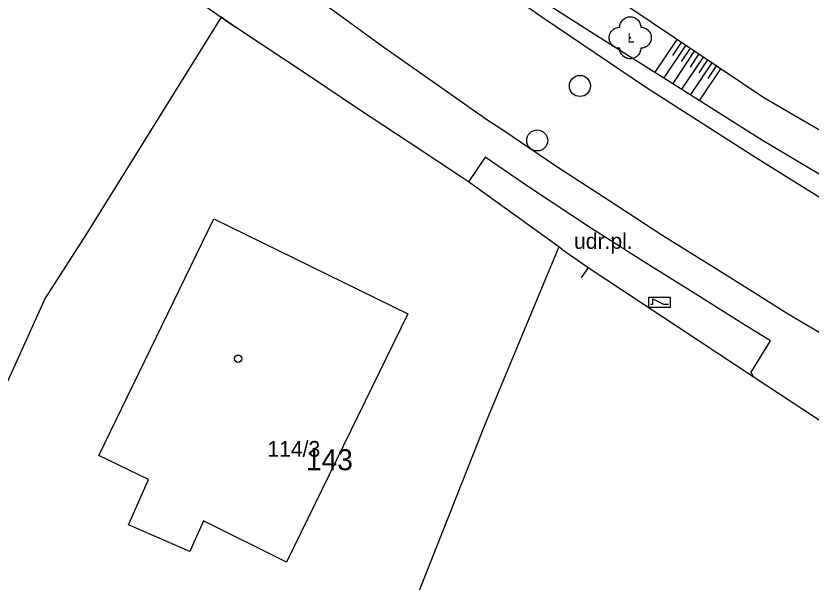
# Model space of a CAD drawing. Extents: x -836568 to -836015, y -1070547 to -1070212.
# Drawn here: x -836460.84 to -836423.06, y -1070392.19 to -1070365.29 of the extents above; entities that cross this region are included whole.
import ezdxf

# ---------------------------------------------------------------- set-up
doc = ezdxf.new("R2010")
doc.units = 0
for name, color, linetype in [('BodPole_mer', 7, 'Continuous'), ('Budovy_hranice', 7, 'Continuous'), ('Budovy_kody', 7, 'Continuous'), ('Doprava_hranice', 7, 'Continuous'), ('PovrZnIS_body', 7, 'Continuous'), ('PovrZnIS_hranice', 7, 'Continuous'), ('RuianAdr_popis', 7, 'Continuous'), ('RuianPar_popis', 7, 'Continuous'), ('Stavby_linie', 7, 'Continuous'), ('Vyskopis_linie', 7, 'Continuous'), ('Zelen_body', 7, 'Continuous'), ('Zelen_kody', 7, 'Continuous')]:
    doc.layers.add(name, color=color, linetype=linetype)

msp = doc.modelspace()

# ---------------------------------------------------------------- linework, layer by layer
at = {"layer": 'BodPole_mer'}
for p, q in [((-836451.09, -1070365.35), (-836451.09, -1070365.35)), ((-836435.85, -1070365.34), (-836435.85, -1070365.34)), ((-836450.4, -1070365.82), (-836450.4, -1070365.82)), ((-836450.4, -1070365.82), (-836450.4, -1070365.82)), ((-836433.66, -1070365.96), (-836433.66, -1070365.96)), ((-836431.65, -1070366.33), (-836431.65, -1070366.33)), ((-836443.36, -1070366.79), (-836443.36, -1070366.79)), ((-836433.37, -1070367.02), (-836433.37, -1070367.02)), ((-836446.93, -1070368.12), (-836446.93, -1070368.12)), ((-836446.93, -1070368.12), (-836446.93, -1070368.12)), ((-836440.92, -1070368.5), (-836440.92, -1070368.5)), ((-836434.04, -1070368.62), (-836434.04, -1070368.62)), ((-836430.87, -1070368.7), (-836430.87, -1070368.7)), ((-836425.3, -1070369.18), (-836425.3, -1070369.18)), ((-836444.56, -1070369.72), (-836444.56, -1070369.72)), ((-836444.56, -1070369.72), (-836444.56, -1070369.72)), ((-836438.47, -1070370.23), (-836438.47, -1070370.23)), ((-836428.32, -1070370.32), (-836428.32, -1070370.32)), ((-836437.61, -1070370.78), (-836437.61, -1070370.78)), ((-836436.07, -1070371.21), (-836436.07, -1070371.21)), ((-836425.36, -1070371.19), (-836425.36, -1070371.19)), ((-836442.16, -1070371.3), (-836442.16, -1070371.3)), ((-836442.16, -1070371.3), (-836442.16, -1070371.3)), ((-836438.55, -1070372.01), (-836438.55, -1070372.01)), ((-836425.77, -1070371.95), (-836425.77, -1070371.95)), ((-836435.14, -1070372.46), (-836435.14, -1070372.46)), ((-836439.62, -1070372.99), (-836439.62, -1070372.99)), ((-836439.62, -1070372.99), (-836439.62, -1070372.99)), ((-836439.34, -1070373.18), (-836439.34, -1070373.18)), ((-836436.43, -1070373.45), (-836436.43, -1070373.45)), ((-836423.24, -1070373.54), (-836423.24, -1070373.54)), ((-836432.62, -1070374.1), (-836432.62, -1070374.1)), ((-836451.44, -1070374.93), (-836451.44, -1070374.93)), ((-836433.49, -1070375.39), (-836433.49, -1070375.39)), ((-836457.52, -1070375.69), (-836457.52, -1070375.69)), ((-836430.1, -1070375.74), (-836430.1, -1070375.74)), ((-836435.05, -1070376.27), (-836435.05, -1070376.27)), ((-836434.9, -1070376.37), (-836434.9, -1070376.37)), ((-836433.65, -1070377.25), (-836433.65, -1070377.25)), ((-836430.97, -1070376.99), (-836430.97, -1070376.99)), ((-836427.55, -1070377.33), (-836427.55, -1070377.33)), ((-836433.98, -1070377.74), (-836433.98, -1070377.74)), ((-836425.85, -1070378.38), (-836425.85, -1070378.38)), ((-836459.45, -1070378.71), (-836459.45, -1070378.71)), ((-836428.41, -1070378.6), (-836428.41, -1070378.6)), ((-836430.26, -1070378.9), (-836430.26, -1070378.9)), ((-836430.26, -1070378.9), (-836430.26, -1070378.9)), ((-836442.21, -1070379.44), (-836442.21, -1070379.44)), ((-836424.17, -1070379.44), (-836424.17, -1070379.44)), ((-836426.3, -1070379.93), (-836426.3, -1070379.93)), ((-836424.98, -1070380.73), (-836424.98, -1070380.73)), ((-836425.91, -1070382.22), (-836425.91, -1070382.22)), ((-836425.81, -1070382.43), (-836425.81, -1070382.43)), ((-836438.54, -1070384.68), (-836438.54, -1070384.68)), ((-836456.9, -1070386.18), (-836456.9, -1070386.18)), ((-836454.54, -1070387.32), (-836454.54, -1070387.32)), ((-836451.92, -1070389.29), (-836451.92, -1070389.29)), ((-836455.49, -1070389.47), (-836455.49, -1070389.47)), ((-836452.57, -1070390.74), (-836452.57, -1070390.74)), ((-836447.98, -1070391.25), (-836447.98, -1070391.25))]:
    msp.add_line(p, q, dxfattribs=at)
at = {"layer": 'Budovy_hranice'}
for p, q in [((-836451.44, -1070374.93), (-836442.21, -1070379.44)), ((-836442.21, -1070379.44), (-836447.98, -1070391.25))]:
    msp.add_line(p, q, dxfattribs=at)
msp.add_lwpolyline([(-836447.98, -1070391.25), (-836451.92, -1070389.29), (-836452.57, -1070390.74), (-836455.49, -1070389.47), (-836454.54, -1070387.32), (-836456.9, -1070386.18), (-836451.44, -1070374.93)], dxfattribs=at)
at = {"layer": 'Budovy_kody'}
msp.add_circle((-836450.28, -1070381.58), 0.175, dxfattribs=at)
at = {"layer": 'Doprava_hranice'}
for points in [[(-836422.05, -1070380.7), (-836424.17, -1070379.44), (-836425.85, -1070378.38), (-836427.55, -1070377.33), (-836430.1, -1070375.74), (-836432.62, -1070374.1), (-836435.14, -1070372.46), (-836437.61, -1070370.78), (-836438.47, -1070370.23), (-836440.92, -1070368.5), (-836443.36, -1070366.79), (-836445.79, -1070365.02), (-836448.77, -1070362.84), (-836451.4, -1070360.84), (-836455.35, -1070357.76), (-836458.47, -1070355.27), (-836461.58, -1070352.77)], [(-836445.19, -1070358.65), (-836443.08, -1070360.18), (-836441.15, -1070361.58), (-836439.46, -1070362.8), (-836438.28, -1070363.63), (-836435.85, -1070365.34), (-836433.37, -1070367.02), (-836430.87, -1070368.7), (-836428.32, -1070370.32), (-836425.77, -1070371.95), (-836423.24, -1070373.54), (-836420.69, -1070375.11)], [(-836425.81, -1070382.43), (-836425.91, -1070382.22), (-836424.98, -1070380.73), (-836426.3, -1070379.93), (-836428.41, -1070378.6), (-836430.97, -1070376.99), (-836433.49, -1070375.39), (-836436.43, -1070373.45), (-836438.55, -1070372.01), (-836439.34, -1070373.18)]]:
    msp.add_lwpolyline(points, dxfattribs=at)
at = {"layer": 'PovrZnIS_body'}
for p, q in [((-836430.76, -1070378.651), (-836429.76, -1070378.649)), ((-836430.76, -1070378.651), (-836429.76, -1070378.649)), ((-836430.76, -1070379.151), (-836430.76, -1070378.651)), ((-836430.76, -1070379.151), (-836430.76, -1070378.651)), ((-836430.571, -1070378.985), (-836430.571, -1070378.735)), ((-836430.571, -1070378.735), (-836430.071, -1070378.984)), ((-836430.571, -1070378.985), (-836430.571, -1070378.735)), ((-836430.571, -1070378.735), (-836430.071, -1070378.984)), ((-836429.76, -1070378.649), (-836429.76, -1070379.149)), ((-836429.76, -1070378.649), (-836429.76, -1070379.149)), ((-836429.76, -1070379.149), (-836430.76, -1070379.151)), ((-836429.76, -1070379.149), (-836430.76, -1070379.151)), ((-836430.681, -1070378.985), (-836430.571, -1070378.985)), ((-836430.681, -1070378.985), (-836430.571, -1070378.985)), ((-836430.071, -1070378.984), (-836429.826, -1070378.983)), ((-836430.071, -1070378.984), (-836429.826, -1070378.983))]:
    msp.add_line(p, q, dxfattribs=at)
for centre in [(-836434.04, -1070368.62), (-836436.07, -1070371.21)]:
    msp.add_circle(centre, 0.5, dxfattribs=at)
at = {"layer": 'PovrZnIS_hranice'}
for p, q in [((-836451.09, -1070365.35), (-836450.4, -1070365.82)), ((-836451.09, -1070365.35), (-836450.4, -1070365.82)), ((-836434.9, -1070376.37), (-836433.65, -1070377.25)), ((-836433.65, -1070377.25), (-836433.98, -1070377.74))]:
    msp.add_line(p, q, dxfattribs=at)
at = {"layer": 'RuianAdr_popis'}
msp.add_line((-836447.06, -1070386.88), (-836447.06, -1070386.88), dxfattribs=at)
at = {"layer": 'RuianPar_popis'}
msp.add_line((-836448.89, -1070386.24), (-836448.89, -1070386.24), dxfattribs=at)
at = {"layer": 'Stavby_linie'}
for p, q in [((-836452.99, -1070364.02), (-836451.09, -1070365.35)), ((-836450.4, -1070365.82), (-836451.09, -1070365.35)), ((-836450.4, -1070365.82), (-836451.09, -1070365.35)), ((-836446.93, -1070368.12), (-836450.4, -1070365.82)), ((-836446.93, -1070368.12), (-836450.4, -1070365.82)), ((-836444.56, -1070369.72), (-836446.93, -1070368.12)), ((-836444.56, -1070369.72), (-836446.93, -1070368.12)), ((-836442.16, -1070371.3), (-836444.56, -1070369.72)), ((-836442.16, -1070371.3), (-836444.56, -1070369.72)), ((-836439.62, -1070372.99), (-836442.16, -1070371.3)), ((-836439.62, -1070372.99), (-836442.16, -1070371.3)), ((-836434.9, -1070376.37), (-836435.05, -1070376.27)), ((-836434.9, -1070376.37), (-836435.05, -1070376.27)), ((-836425.81, -1070382.43), (-836422.29, -1070384.74))]:
    msp.add_line(p, q, dxfattribs=at)
for points in [[(-836451.09, -1070365.35), (-836457.52, -1070375.69), (-836459.45, -1070378.71), (-836464.64, -1070390.16), (-836469.09, -1070399.98), (-836470.4, -1070403.24)], [(-836435.05, -1070376.27), (-836439.34, -1070373.18), (-836439.62, -1070372.99)], [(-836435.05, -1070376.27), (-836438.54, -1070384.68), (-836445.25, -1070401.61), (-836449.39, -1070412.25)], [(-836434.9, -1070376.37), (-836433.65, -1070377.25), (-836425.81, -1070382.43)]]:
    msp.add_lwpolyline(points, dxfattribs=at)
at = {"layer": 'Vyskopis_linie'}
for p, q in [((-836429.44, -1070366.41), (-836430.48, -1070367.97)), ((-836429.02, -1070366.69), (-836430.05, -1070368.23)), ((-836429.23, -1070366.55), (-836429.64, -1070367.17)), ((-836428.61, -1070366.97), (-836429.63, -1070368.5)), ((-836428.81, -1070366.83), (-836429.23, -1070367.45)), ((-836428.4, -1070367.11), (-836428.81, -1070367.72)), ((-836428.19, -1070367.25), (-836429.21, -1070368.77)), ((-836427.98, -1070367.38), (-836428.39, -1070367.99)), ((-836427.77, -1070367.52), (-836428.78, -1070369.03)), ((-836427.36, -1070367.8), (-836428.36, -1070369.3)), ((-836427.57, -1070367.66), (-836427.97, -1070368.27))]:
    msp.add_line(p, q, dxfattribs=at)
for points in [[(-836434.23, -1070354.27), (-836438.23, -1070358.57), (-836440.17, -1070361.78), (-836433.66, -1070365.96), (-836425.36, -1070371.19), (-836413.35, -1070378.34), (-836408.55, -1070381.18), (-836406.45, -1070381.27), (-836403.31, -1070376.81), (-836398.57, -1070364.21), (-836395.25, -1070356.24), (-836395.84, -1070356.16)], [(-836395.84, -1070356.16), (-836401.02, -1070368.01), (-836403.57, -1070374.4), (-836406.76, -1070379.93), (-836408.49, -1070379.57), (-836416.6, -1070374.24), (-836425.3, -1070369.18), (-836431.77, -1070364.85), (-836437.84, -1070361.03), (-836434.23, -1070354.27)]]:
    msp.add_lwpolyline(points, dxfattribs=at)
at = {"layer": 'Zelen_body'}
msp.add_line((-836431.65, -1070366.33), (-836431.65, -1070366.33), dxfattribs=at)
for points in [[(-836432.15, -1070365.83), (-836432.148, -1070365.782), (-836432.14, -1070365.733), (-836432.128, -1070365.683), (-836432.11, -1070365.634), (-836432.086, -1070365.585), (-836432.057, -1070365.539), (-836432.023, -1070365.496), (-836431.984, -1070365.457), (-836431.941, -1070365.423), (-836431.895, -1070365.394), (-836431.846, -1070365.37), (-836431.797, -1070365.352), (-836431.747, -1070365.34), (-836431.698, -1070365.332), (-836431.65, -1070365.33), (-836431.602, -1070365.332), (-836431.553, -1070365.34), (-836431.503, -1070365.352), (-836431.454, -1070365.37), (-836431.405, -1070365.394), (-836431.359, -1070365.423), (-836431.316, -1070365.457), (-836431.277, -1070365.496), (-836431.243, -1070365.539), (-836431.214, -1070365.585), (-836431.19, -1070365.634), (-836431.172, -1070365.683), (-836431.16, -1070365.733), (-836431.152, -1070365.782), (-836431.15, -1070365.83)], [(-836432.15, -1070366.83), (-836432.198, -1070366.828), (-836432.247, -1070366.82), (-836432.297, -1070366.808), (-836432.346, -1070366.79), (-836432.395, -1070366.766), (-836432.441, -1070366.737), (-836432.484, -1070366.703), (-836432.523, -1070366.664), (-836432.557, -1070366.621), (-836432.586, -1070366.575), (-836432.61, -1070366.526), (-836432.628, -1070366.477), (-836432.64, -1070366.427), (-836432.648, -1070366.378), (-836432.65, -1070366.33), (-836432.648, -1070366.282), (-836432.64, -1070366.233), (-836432.628, -1070366.183), (-836432.61, -1070366.134), (-836432.586, -1070366.085), (-836432.557, -1070366.039), (-836432.523, -1070365.996), (-836432.484, -1070365.957), (-836432.441, -1070365.923), (-836432.395, -1070365.894), (-836432.346, -1070365.87), (-836432.297, -1070365.852), (-836432.247, -1070365.84), (-836432.198, -1070365.832), (-836432.15, -1070365.83)], [(-836431.15, -1070365.83), (-836431.102, -1070365.832), (-836431.053, -1070365.84), (-836431.003, -1070365.852), (-836430.954, -1070365.87), (-836430.905, -1070365.894), (-836430.859, -1070365.923), (-836430.816, -1070365.957), (-836430.777, -1070365.996), (-836430.743, -1070366.039), (-836430.714, -1070366.085), (-836430.69, -1070366.134), (-836430.672, -1070366.183), (-836430.66, -1070366.233), (-836430.652, -1070366.282), (-836430.65, -1070366.33), (-836430.652, -1070366.378), (-836430.66, -1070366.427), (-836430.672, -1070366.477), (-836430.69, -1070366.526), (-836430.714, -1070366.575), (-836430.743, -1070366.621), (-836430.777, -1070366.664), (-836430.816, -1070366.703), (-836430.859, -1070366.737), (-836430.905, -1070366.766), (-836430.954, -1070366.79), (-836431.003, -1070366.808), (-836431.053, -1070366.82), (-836431.102, -1070366.828), (-836431.15, -1070366.83)], [(-836431.15, -1070366.83), (-836431.152, -1070366.878), (-836431.16, -1070366.927), (-836431.172, -1070366.977), (-836431.19, -1070367.026), (-836431.214, -1070367.075), (-836431.243, -1070367.121), (-836431.277, -1070367.164), (-836431.316, -1070367.203), (-836431.359, -1070367.237), (-836431.405, -1070367.266), (-836431.454, -1070367.29), (-836431.503, -1070367.308), (-836431.553, -1070367.32), (-836431.602, -1070367.328), (-836431.65, -1070367.33), (-836431.698, -1070367.328), (-836431.747, -1070367.32), (-836431.797, -1070367.308), (-836431.846, -1070367.29), (-836431.895, -1070367.266), (-836431.941, -1070367.237), (-836431.984, -1070367.203), (-836432.023, -1070367.164), (-836432.057, -1070367.121), (-836432.086, -1070367.075), (-836432.11, -1070367.026), (-836432.128, -1070366.977), (-836432.14, -1070366.927), (-836432.148, -1070366.878), (-836432.15, -1070366.83)]]:
    msp.add_lwpolyline(points, dxfattribs=at)
msp.add_ellipse((-836431.65, -1070366.33), major_axis=(0.025, 0), ratio=0.999997, dxfattribs=at)

# ---------------------------------------------------------------- texts
at = {"layer": 'RuianAdr_popis'}
msp.add_text('143', height=1, dxfattribs=at).set_placement((-836447.06, -1070386.88))
at = {"layer": 'RuianPar_popis'}
msp.add_text('114/3', height=0.75, dxfattribs=at).set_placement((-836448.89, -1070386.24))
at = {"layer": 'Zelen_body'}
msp.add_text('L', height=0.45, dxfattribs=at).set_placement((-836431.781, -1070366.555))
at = {"layer": 'Zelen_kody'}
msp.add_text('udr.pl.', height=0.75, dxfattribs=at).set_placement((-836434.32, -1070376.36))

doc.saveas('drawing.dxf')
